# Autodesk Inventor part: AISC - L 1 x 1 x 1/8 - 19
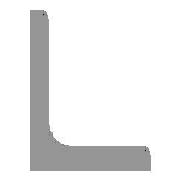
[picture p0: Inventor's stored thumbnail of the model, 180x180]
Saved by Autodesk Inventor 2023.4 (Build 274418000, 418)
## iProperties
IsCustomPart: 1
Created: 2023-10
Part Number: AISC - L 1 x 1 x 1/8 - 19
Material: Steel, Mild
Description: Angle Steel
Document SubType Name: Modeling
Standard: AISC
Designer: Fred L.
Standards Organization: ANSI
Language: en-US
Size Designation: (L 1 x 1 x 1/8)
Categories: <MemberInstance><Categories><Category DisplayName="Structural Shapes" InternalName="089c4875-fa83-4c05-b084-43b9cc11f5ed" Mnemonic="GRDR"><CategoryParameter Dis
Stock Number: (L 1 x 1 x 1/8)
Mass: 576.091 g
Surface Area: 479.71 cm^2
Volume: 73.3873 cm^3
Density: 7.85 g/cm^3
Appearance: Semi-Polished
_CCFamilyMember: 1
_CCFamilyDisplayName: ANSI L (Equal angles) - Angle Steel — Sizes in parentheses have been withdrawn
_FrameMemberDoc: Frame Member File
_Version: 25.0.0
_GetPNFromCC: 1
G_L: 19.000 in
G_W: 1.000 in
G_H: 1.000 in
Mass: 1.27
SurfaceArea: 74.36
+4A91A003-9ACF-4524-891B-5FEE60D6CC2A+CUTDETAIL1: Corner Joint
+586499EA-E712-4C99-99F7-965C7F7844D1+CUTDETAIL2: Corner Joint
Author: Fred L.
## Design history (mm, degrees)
node "Start Plane"
node "End Plane"
sketch "Sketch"
  geometry: L1 (25.4, 0)-(0, 0); L2 (0, 0)-(0, 25.4); L3 (0, 25.4)-(1.651, 25.4); L4 (3.175, 23.876)-(3.175, 6.477); L5 (6.477, 3.175)-(23.876, 3.175); L6 (25.4, 1.651)-(25.4, 0); L7 (0, -11.041)-(0, 31.538); L8 (-11.041, 0)-(31.538, 0); L9 (0, 40.054)-(0, -19.557) reference; L10 (-19.557, 0)-(40.054, 0) reference; A1 r 3.302 centre (6.477, 6.477) between (3.175, 6.477) and (6.477, 3.175); A2 r 1.524 centre (1.651, 23.876) between (3.175, 23.876) and (1.651, 25.4); A3 r 1.524 centre (23.876, 1.651) between (25.4, 1.651) and (23.876, 3.175); 3 further points
  constraints: 16 end point, 6 point on circle, 6 point on line, 6 tangent, 4 parallel, 3 centre point, 2 collinear, 1 equal radius, 1 horizontal, 1 perpendicular
  dimensions: "d0" = 25.4 distance between parallel lines of L6 L2 (= G_H); "d1" = 25.4 distance between parallel lines of L3 L1 (= G_H); "d2" = 3.175 distance between parallel lines of L2 L4 (= G_T); "d3" = 3.175 distance between parallel lines of L1 L5 (= G_T); "d10" = 0 distance between parallel lines of L7 L2 (computed from ex); "d11" = 0 distance between parallel lines of L8 L1 (computed from d10); "d14" = 3.302 radius of A1 (= G_IR); "d15" = 1.524 radius of A2 (= G_ER)
extrude "Body" new body sketch "Sketch" stored distance "d4" = 482.6 (= G_L); taper "d5" = 0 deg
node "Driven Length"
  sketch "Sketch3"
    geometry: L1 (0, 0)-(10, 0) reference
    constraints: 2 end point, 1 horizontal
  workplane "Work Plane3"
workplane "Work Plane4"
split "Split1"
workplane "Work Plane5"
split "Split2"
sketch "Sketch5"
  geometry: C1 r 4.848 at (329.777, 9.246); 1 further point
  constraints: 1 centre point
extrude "Extrusion2" cut sketch "Sketch5" distance "d18" = 25.4; taper "d19" = 0 deg
body "Solid1"
sketch "Sketch4"
  geometry: L1 (-2, 12.7)-(12, 12.7) reference; L2 (-2, 495.3)-(12, 495.3) reference
  dimensions: "d17" = 482.6 distance between parallel lines of L1 L2 (derived)
other parameters: "G_H" = 25.4 [user parameter; used in 2 equation terms], "G_T" = 3.175 [user parameter; used in 2 equation terms], "G_ER" = 1.524 [user parameter; used in 1 equation term], "G_IR" = 3.302 [user parameter; used in 1 equation term], "G_L" = 482.6 (= d17) [user parameter; used in 1 equation term], "ex" = 0 [user parameter; used in 1 equation term], "G_OFFSET_START" = -12.7 [user parameter; used in 1 equation term], "G_OFFSET_END" = -12.7 [user parameter; used in 1 equation term], "d12" = 12.7 (= -G_OFFSET_START), "d13" = 495.3 (= G_OFFSET_END + B_L), "B_L" = 508 [user parameter; used in 1 equation term], "d16" = 90 deg, "MAS" = 0.11905 [user parameter]
